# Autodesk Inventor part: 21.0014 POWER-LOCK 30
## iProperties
Created: 2012-02
Part Number: 21.0014 POWER-LOCK 30
Document SubType Name: Modeling
Designer: Administrator
Density: 7.85 g/cm^3
Material: Steel
Mass: 23.5605 g
Surface Area: 21.8098 cm^2
Volume: 3.00134 cm^3
Translation Standard: STEP AP214IS
FileName: 21_0014_0_1.stp
PreProcessor: ACIS
PostProcessor: Build: 236a, Release: 2009 RTM - Date: Fri 02/22/2008
Sent Units: MM
Uncertainty: 1e-06
Author: Administrator
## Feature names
1. Base1
